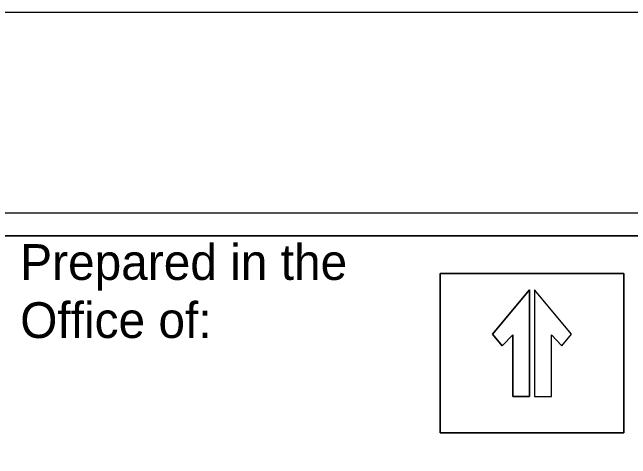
# Model space of a CAD drawing. Extents: x 1629887 to 1632095, y 1174261 to 1175361.
# Drawn here: x 1631155.4 to 1631224.6, y 1175310.9 to 1175360.8 of the extents above; entities that cross this region are included whole.
import ezdxf

# ---------------------------------------------------------------- set-up
doc = ezdxf.new("R2010")
doc.units = 0
for name, color, linetype in [('Sheet Block Title CELL', 7, 'Continuous'), ('Sheet Plot Border Inside CELL', 7, 'Continuous'), ('Sheet Plot Border Outside CELL', 7, 'Continuous'), ('Sheet Profile CELL', 7, 'Continuous')]:
    doc.layers.add(name, color=color, linetype=linetype)

msp = doc.modelspace()

# ---------------------------------------------------------------- linework, layer by layer
at = {"layer": 'Sheet Block Title CELL'}
for points in [[(1631154.206, 1175335.787), (1631354.264, 1175335.787), (1631354.264, 1175309.531), (1631154.206, 1175309.531)], [(1631203.309, 1175331.58), (1631223.866, 1175331.58), (1631223.866, 1175313.737), (1631203.309, 1175313.737)], [(1631213.888, 1175329.755), (1631213.888, 1175317.825), (1631215.767, 1175317.825), (1631215.767, 1175324.706), (1631216.931, 1175323.474), (1631218.026, 1175324.781)]]:
    msp.add_lwpolyline(points, close=True, dxfattribs=at)
for points in [[(1631223.866, 1175331.58), (1631203.309, 1175331.58), (1631203.309, 1175313.737), (1631223.866, 1175313.737), (1631223.866, 1175331.58)], [(1631213.31, 1175329.755), (1631213.31, 1175317.825), (1631211.43, 1175317.825), (1631211.43, 1175324.706), (1631210.266, 1175323.474), (1631209.172, 1175324.781), (1631213.31, 1175329.755)], [(1631209.172, 1175324.781), (1631210.266, 1175323.474), (1631211.43, 1175324.706), (1631211.43, 1175317.825), (1631213.31, 1175317.825), (1631213.31, 1175329.755), (1631209.172, 1175324.781)], [(1631213.888, 1175329.755), (1631213.888, 1175317.825), (1631215.767, 1175317.825), (1631215.767, 1175324.706), (1631216.931, 1175323.474), (1631218.026, 1175324.781), (1631213.888, 1175329.755)]]:
    msp.add_lwpolyline(points, dxfattribs=at)
at = {"layer": 'Sheet Plot Border Inside CELL'}
msp.add_lwpolyline([(1629900.314, 1174283.237), (1631566.814, 1174283.237), (1631566.814, 1175338.337), (1629900.314, 1175338.337)], close=True, dxfattribs=at)
at = {"layer": 'Sheet Plot Border Outside CELL'}
msp.add_lwpolyline([(1629887.314, 1174260.787), (1631571.314, 1174260.787), (1631571.314, 1175360.787), (1629887.314, 1175360.787)], close=True, dxfattribs=at)
at = {"layer": 'Sheet Profile CELL'}
msp.add_lwpolyline([(1631554.314, 1175335.787), (1630054.314, 1175335.787), (1630054.314, 1174285.787), (1631554.314, 1174285.787)], close=True, dxfattribs=at)

# ---------------------------------------------------------------- texts
at = {"layer": 'Sheet Block Title CELL'}
for s, height, p in [('Prepared in the ', 4.00116, (1631156.328, 1175330.853)), ('Office of:', 4.0012, (1631156.328, 1175324.351))]:
    msp.add_text(s, height=height, rotation=360, dxfattribs=at).set_placement(p)

doc.saveas('drawing.dxf')
